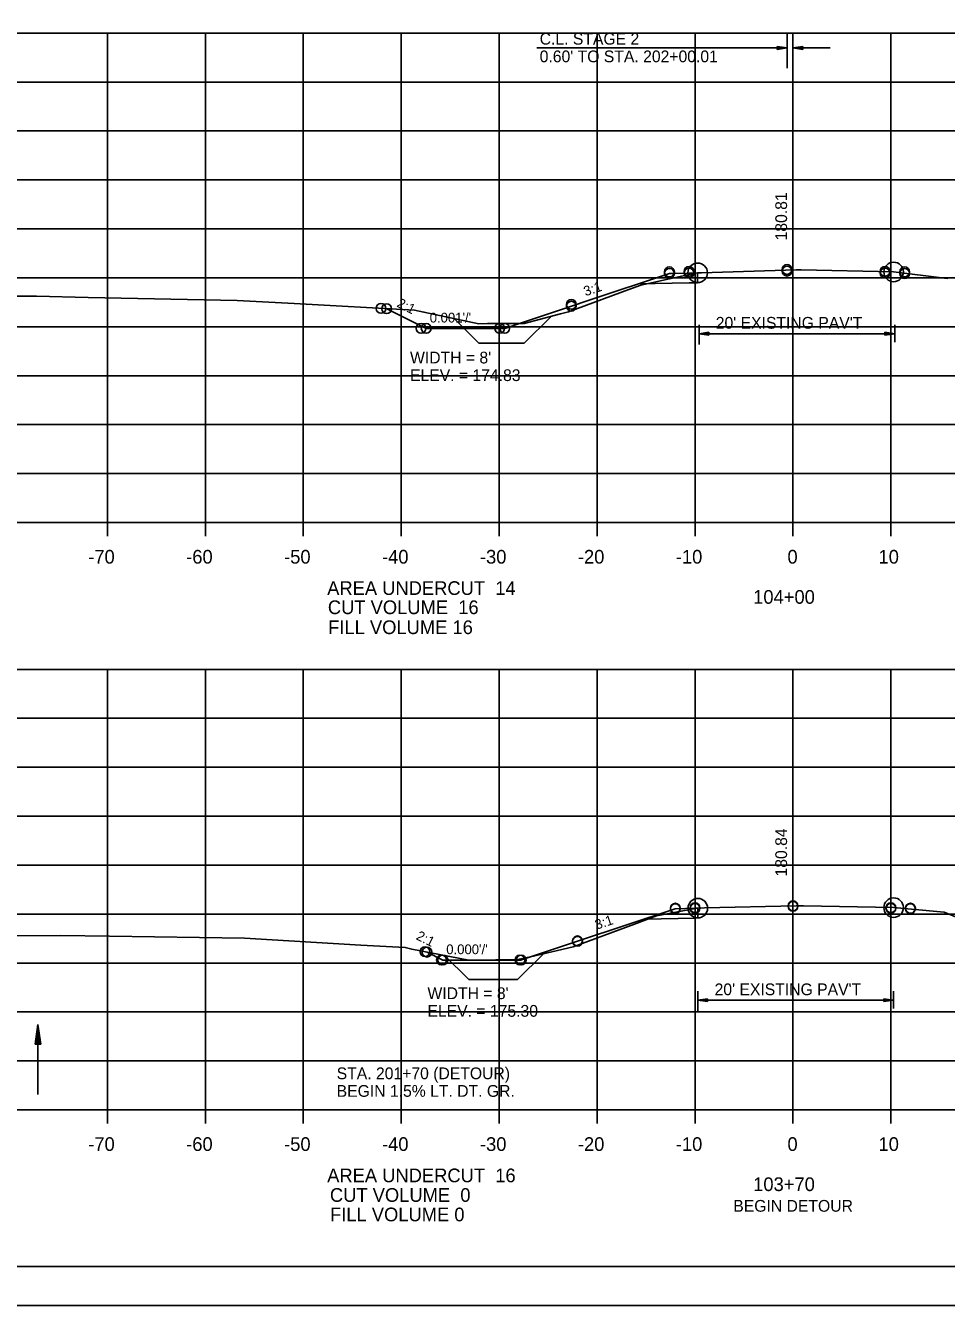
# Model space of a CAD drawing. Extents: x 1372132 to 1372465, y 380083 to 381790.
# Drawn here: x 1372223.7 to 1372317.7, y 380083.5 to 380214.2 of the extents above; entities that cross this region are included whole.
import ezdxf

# ---------------------------------------------------------------- set-up
doc = ezdxf.new("R2010")
doc.units = 0
for name, color, linetype in [('R_Alt Surface', 7, 'Continuous'), ('R_Axis', 7, 'Continuous'), ('R_Axis Annot', 7, 'Continuous'), ('R_Border', 7, 'Continuous'), ('R_Dimension', 7, 'Continuous'), ('R_Draft', 7, 'Continuous'), ('R_Erosion', 7, 'Continuous'), ('R_Exist Surface', 7, 'Continuous'), ('R_Fin Surface', 7, 'Continuous'), ('R_Grid', 7, 'Continuous'), ('R_No Plot', 7, 'Continuous'), ('R_Xsect Elev', 7, 'Continuous'), ('R_Xsect Slope', 7, 'Continuous')]:
    doc.layers.add(name, color=color, linetype=linetype)

msp = doc.modelspace()

# ---------------------------------------------------------------- linework, layer by layer
at = {"layer": 'R_Alt Surface'}
for points in [[(1372292.28, 380187.97), (1372291.4, 380187.95), (1372286.21, 380187.85)], [(1372292.31, 380123.07), (1372292.01, 380123.06), (1372286.82, 380122.96)]]:
    msp.add_lwpolyline(points, dxfattribs=at)
at = {"layer": 'R_Axis'}
for p, q in [((1372162.01, 380163.47), (1372442.01, 380163.47)), ((1372232.01, 380162.07), (1372232.01, 380163.47)), ((1372242.01, 380162.07), (1372242.01, 380163.47)), ((1372252.01, 380162.07), (1372252.01, 380163.47)), ((1372262.01, 380162.07), (1372262.01, 380163.47)), ((1372272.01, 380162.07), (1372272.01, 380163.47)), ((1372282.01, 380162.07), (1372282.01, 380163.47)), ((1372292.01, 380162.07), (1372292.01, 380163.47)), ((1372302.01, 380162.07), (1372302.01, 380163.47)), ((1372312.01, 380162.07), (1372312.01, 380163.47)), ((1372162.01, 380103.47), (1372442.01, 380103.47)), ((1372232.01, 380102.07), (1372232.01, 380103.47)), ((1372242.01, 380102.07), (1372242.01, 380103.47)), ((1372252.01, 380102.07), (1372252.01, 380103.47)), ((1372262.01, 380102.07), (1372262.01, 380103.47)), ((1372272.01, 380102.07), (1372272.01, 380103.47)), ((1372282.01, 380102.07), (1372282.01, 380103.47)), ((1372292.01, 380102.07), (1372292.01, 380103.47)), ((1372302.01, 380102.07), (1372302.01, 380103.47)), ((1372312.01, 380102.07), (1372312.01, 380103.47))]:
    msp.add_line(p, q, dxfattribs=at)
at = {"layer": 'R_Border'}
msp.add_line((1372460.19, 380087.47), (1372144.01, 380087.47), dxfattribs=at)
at = {"layer": 'R_Dimension'}
for p, q in [((1372224.62, 380110.18), (1372224.92, 380112.18)), ((1372224.62, 380110.18), (1372224.92, 380112.18)), ((1372224.67, 380110.18), (1372224.92, 380111.85)), ((1372224.67, 380110.18), (1372224.92, 380111.85)), ((1372224.72, 380110.18), (1372224.92, 380111.51)), ((1372224.72, 380110.18), (1372224.92, 380111.51)), ((1372224.77, 380110.18), (1372224.92, 380111.17)), ((1372224.77, 380110.18), (1372224.92, 380111.17)), ((1372225.22, 380110.18), (1372224.92, 380112.18)), ((1372225.22, 380110.18), (1372224.92, 380112.18)), ((1372225.17, 380110.18), (1372224.92, 380111.85)), ((1372225.17, 380110.18), (1372224.92, 380111.85)), ((1372225.12, 380110.18), (1372224.92, 380111.51)), ((1372225.12, 380110.18), (1372224.92, 380111.51)), ((1372225.07, 380110.18), (1372224.92, 380111.17)), ((1372225.07, 380110.18), (1372224.92, 380111.17)), ((1372224.62, 380110.18), (1372225.22, 380110.18)), ((1372224.62, 380110.18), (1372225.22, 380110.18)), ((1372224.83, 380110.18), (1372224.92, 380110.83)), ((1372224.83, 380110.18), (1372224.92, 380110.83)), ((1372224.88, 380110.18), (1372224.92, 380110.5)), ((1372224.88, 380110.18), (1372224.92, 380110.5)), ((1372225.02, 380110.18), (1372224.92, 380110.83)), ((1372225.02, 380110.18), (1372224.92, 380110.83)), ((1372224.97, 380110.18), (1372224.92, 380110.5)), ((1372224.97, 380110.18), (1372224.92, 380110.5))]:
    msp.add_line(p, q, dxfattribs=at)
at = {"layer": 'R_Draft'}
for p, q in [((1372301.41, 380209.88), (1372301.41, 380213.47)), ((1372302.01, 380213.47), (1372302.01, 380209.88)), ((1372275.87, 380211.96), (1372301.41, 380211.96)), ((1372300.41, 380212.11), (1372301.41, 380211.96)), ((1372300.41, 380212.11), (1372300.41, 380211.81)), ((1372300.41, 380212.11), (1372301.41, 380211.96)), ((1372300.41, 380212.11), (1372300.41, 380211.81)), ((1372300.41, 380212.09), (1372301.25, 380211.96)), ((1372300.41, 380212.09), (1372301.25, 380211.96)), ((1372300.41, 380212.06), (1372301.07, 380211.96)), ((1372300.41, 380212.06), (1372301.07, 380211.96)), ((1372300.41, 380212.04), (1372300.91, 380211.96)), ((1372300.41, 380212.04), (1372300.91, 380211.96)), ((1372300.41, 380212.01), (1372300.74, 380211.96)), ((1372300.41, 380212.01), (1372300.74, 380211.96)), ((1372300.41, 380211.99), (1372300.57, 380211.96)), ((1372300.41, 380211.99), (1372300.57, 380211.96)), ((1372300.41, 380211.81), (1372301.41, 380211.96)), ((1372300.41, 380211.91), (1372300.74, 380211.96)), ((1372300.41, 380211.86), (1372301.07, 380211.96)), ((1372300.41, 380211.84), (1372301.25, 380211.96)), ((1372300.41, 380211.89), (1372300.91, 380211.96)), ((1372300.41, 380211.94), (1372300.57, 380211.96)), ((1372300.41, 380211.81), (1372301.41, 380211.96)), ((1372300.41, 380211.91), (1372300.74, 380211.96)), ((1372300.41, 380211.86), (1372301.07, 380211.96)), ((1372300.41, 380211.84), (1372301.25, 380211.96)), ((1372300.41, 380211.89), (1372300.91, 380211.96)), ((1372300.41, 380211.94), (1372300.57, 380211.96)), ((1372303.01, 380212.11), (1372302.01, 380211.96)), ((1372302.01, 380211.96), (1372305.82, 380211.96)), ((1372303.01, 380211.81), (1372302.01, 380211.96)), ((1372303.01, 380212.09), (1372302.18, 380211.96)), ((1372303.01, 380211.84), (1372302.18, 380211.96)), ((1372303.01, 380212.06), (1372302.35, 380211.96)), ((1372303.01, 380211.86), (1372302.35, 380211.96)), ((1372303.01, 380212.04), (1372302.52, 380211.96)), ((1372303.01, 380211.89), (1372302.52, 380211.96)), ((1372303.01, 380212.01), (1372302.69, 380211.96)), ((1372303.01, 380211.91), (1372302.69, 380211.96)), ((1372303.01, 380211.99), (1372302.86, 380211.96)), ((1372303.01, 380211.94), (1372302.86, 380211.96)), ((1372303.01, 380211.81), (1372303.01, 380212.11)), ((1372292.28, 380188.97), (1372292.28, 380187.97)), ((1372292.43, 380183.67), (1372292.43, 380181.66)), ((1372293.43, 380182.91), (1372292.43, 380182.76)), ((1372293.43, 380182.91), (1372292.43, 380182.76)), ((1372293.43, 380182.88), (1372292.59, 380182.76)), ((1372293.43, 380182.88), (1372292.59, 380182.76)), ((1372293.43, 380182.86), (1372292.77, 380182.76)), ((1372293.43, 380182.86), (1372292.77, 380182.76)), ((1372293.43, 380182.61), (1372293.43, 380182.91)), ((1372293.43, 380182.61), (1372293.43, 380182.91)), ((1372311.41, 380182.91), (1372312.41, 380182.76)), ((1372311.41, 380182.91), (1372311.41, 380182.61)), ((1372311.41, 380182.88), (1372312.24, 380182.76)), ((1372311.41, 380182.86), (1372312.07, 380182.76)), ((1372312.41, 380183.67), (1372312.41, 380181.9)), ((1372312.41, 380182.76), (1372292.43, 380182.76)), ((1372293.43, 380182.61), (1372292.43, 380182.76)), ((1372293.43, 380182.61), (1372292.43, 380182.76)), ((1372292.43, 380181.9), (1372292.43, 380181.9)), ((1372293.43, 380182.63), (1372292.59, 380182.76)), ((1372293.43, 380182.63), (1372292.59, 380182.76)), ((1372293.43, 380182.66), (1372292.77, 380182.76)), ((1372293.43, 380182.66), (1372292.77, 380182.76)), ((1372293.43, 380182.83), (1372292.93, 380182.76)), ((1372293.43, 380182.83), (1372292.93, 380182.76)), ((1372293.43, 380182.68), (1372292.93, 380182.76)), ((1372293.43, 380182.68), (1372292.93, 380182.76)), ((1372293.43, 380182.8), (1372293.1, 380182.76)), ((1372293.43, 380182.8), (1372293.1, 380182.76)), ((1372293.43, 380182.71), (1372293.1, 380182.76)), ((1372293.43, 380182.71), (1372293.1, 380182.76)), ((1372293.43, 380182.78), (1372293.27, 380182.76)), ((1372293.43, 380182.78), (1372293.27, 380182.76)), ((1372293.43, 380182.73), (1372293.27, 380182.76)), ((1372293.43, 380182.73), (1372293.27, 380182.76)), ((1372311.41, 380182.83), (1372311.9, 380182.76)), ((1372311.41, 380182.8), (1372311.73, 380182.76)), ((1372311.41, 380182.78), (1372311.57, 380182.76)), ((1372311.41, 380182.61), (1372312.41, 380182.76)), ((1372311.41, 380182.71), (1372311.73, 380182.76)), ((1372311.41, 380182.66), (1372312.07, 380182.76)), ((1372311.41, 380182.63), (1372312.24, 380182.76)), ((1372311.41, 380182.68), (1372311.9, 380182.76)), ((1372311.41, 380182.73), (1372311.57, 380182.76)), ((1372292.3, 380124.07), (1372292.3, 380123.07)), ((1372292.3, 380115.58), (1372292.3, 380113.57)), ((1372312.29, 380115.58), (1372312.29, 380113.81)), ((1372293.3, 380114.82), (1372292.3, 380114.67)), ((1372293.3, 380114.82), (1372292.3, 380114.67)), ((1372312.29, 380114.67), (1372292.3, 380114.67)), ((1372293.3, 380114.52), (1372292.3, 380114.67)), ((1372293.3, 380114.52), (1372292.3, 380114.67)), ((1372292.3, 380113.81), (1372292.3, 380113.81)), ((1372293.3, 380114.79), (1372292.47, 380114.67)), ((1372293.3, 380114.79), (1372292.47, 380114.67)), ((1372293.3, 380114.54), (1372292.47, 380114.67)), ((1372293.3, 380114.54), (1372292.47, 380114.67)), ((1372293.3, 380114.77), (1372292.64, 380114.67)), ((1372293.3, 380114.77), (1372292.64, 380114.67)), ((1372293.3, 380114.57), (1372292.64, 380114.67)), ((1372293.3, 380114.57), (1372292.64, 380114.67)), ((1372293.3, 380114.74), (1372292.81, 380114.67)), ((1372293.3, 380114.74), (1372292.81, 380114.67)), ((1372293.3, 380114.59), (1372292.81, 380114.67)), ((1372293.3, 380114.59), (1372292.81, 380114.67)), ((1372293.3, 380114.71), (1372292.98, 380114.67)), ((1372293.3, 380114.71), (1372292.98, 380114.67)), ((1372293.3, 380114.62), (1372292.98, 380114.67)), ((1372293.3, 380114.62), (1372292.98, 380114.67)), ((1372293.3, 380114.69), (1372293.15, 380114.67)), ((1372293.3, 380114.69), (1372293.15, 380114.67)), ((1372293.3, 380114.64), (1372293.15, 380114.67)), ((1372293.3, 380114.64), (1372293.15, 380114.67)), ((1372293.3, 380114.52), (1372293.3, 380114.82)), ((1372293.3, 380114.52), (1372293.3, 380114.82)), ((1372311.29, 380114.82), (1372312.29, 380114.67)), ((1372311.29, 380114.82), (1372311.29, 380114.52)), ((1372311.29, 380114.79), (1372312.12, 380114.67)), ((1372311.29, 380114.77), (1372311.95, 380114.67)), ((1372311.29, 380114.74), (1372311.78, 380114.67)), ((1372311.29, 380114.71), (1372311.61, 380114.67)), ((1372311.29, 380114.69), (1372311.44, 380114.67)), ((1372311.29, 380114.52), (1372312.29, 380114.67)), ((1372311.29, 380114.62), (1372311.61, 380114.67)), ((1372311.29, 380114.57), (1372311.95, 380114.67)), ((1372311.29, 380114.54), (1372312.12, 380114.67)), ((1372311.29, 380114.59), (1372311.78, 380114.67)), ((1372311.29, 380114.64), (1372311.44, 380114.67)), ((1372224.92, 380105.04), (1372224.92, 380112.18))]:
    msp.add_line(p, q, dxfattribs=at)
at = {"layer": 'R_Erosion'}
for p, q in [((1372269.94, 380181.78), (1372267.42, 380184.31)), ((1372274.57, 380181.78), (1372277.32, 380184.53)), ((1372269.94, 380181.78), (1372274.57, 380181.78)), ((1372268.9, 380116.78), (1372266.41, 380119.27)), ((1372273.9, 380116.78), (1372276.54, 380119.41)), ((1372268.9, 380116.78), (1372273.9, 380116.78))]:
    msp.add_line(p, q, dxfattribs=at)
at = {"layer": 'R_Exist Surface'}
for points in [[(1372222.51, 380186.6), (1372224.77, 380186.58), (1372230.03, 380186.47), (1372245.27, 380186.15), (1372251.07, 380185.83), (1372263.36, 380185.15), (1372264.32, 380184.96), (1372269.95, 380183.78), (1372270.82, 380183.79), (1372274.57, 380183.79), (1372278.29, 380184.79), (1372279.09, 380184.99), (1372285.25, 380187.28), (1372286.48, 380187.73), (1372292.04, 380188.93), (1372292.28, 380188.98), (1372292.69, 380188.99), (1372302.34, 380189.3), (1372302.84, 380189.29), (1372312.29, 380189.07), (1372317.48, 380188.44), (1372317.82, 380188.4)], [(1372175.77, 380121.19), (1372195.26, 380121.23), (1372227.21, 380121.29), (1372232.22, 380121.2), (1372246.02, 380120.99), (1372257.87, 380120.28), (1372262.42, 380120.07), (1372263.09, 380119.88), (1372268.91, 380118.77), (1372269.44, 380118.77), (1372273.89, 380118.84), (1372275.21, 380119.11), (1372279.58, 380120.12), (1372285.82, 380122.43), (1372288.07, 380123.3), (1372292.02, 380124.03), (1372292.3, 380124.07), (1372292.99, 380124.09), (1372302.34, 380124.32), (1372303.1, 380124.31), (1372312.29, 380124.13), (1372317.08, 380123.7), (1372317.45, 380123.67), (1372325.71, 380120.28)]]:
    msp.add_lwpolyline(points, dxfattribs=at)
at = {"layer": 'R_Fin Surface'}
for points in [[(1372260.53, 380185.31), (1372261.97, 380184.59), (1372264.56, 380183.3), (1372266.93, 380183.3), (1372272.58, 380183.3), (1372274.18, 380183.84), (1372279.39, 380185.57), (1372281.09, 380186.14), (1372289.4, 380188.91), (1372289.6, 380188.91), (1372291.4, 380188.95), (1372292.28, 380188.97)], [(1372264.65, 380119.58), (1372264.65, 380119.58), (1372266.26, 380118.77), (1372266.28, 380118.77), (1372274.26, 380118.77), (1372274.28, 380118.78), (1372280.01, 380120.69), (1372289.99, 380124.01), (1372290.01, 380124.02), (1372292.01, 380124.06), (1372292.01, 380124.06), (1372292.31, 380124.07)]]:
    msp.add_lwpolyline(points, dxfattribs=at)
at = {"layer": 'R_Grid'}
for p, q in [((1372162.01, 380213.47), (1372442.01, 380213.47)), ((1372232.01, 380163.47), (1372232.01, 380213.47)), ((1372242.01, 380163.47), (1372242.01, 380213.47)), ((1372252.01, 380163.47), (1372252.01, 380213.47)), ((1372262.01, 380163.47), (1372262.01, 380213.47)), ((1372272.01, 380163.47), (1372272.01, 380213.47)), ((1372282.01, 380163.47), (1372282.01, 380213.47)), ((1372292.01, 380163.47), (1372292.01, 380213.47)), ((1372302.01, 380163.47), (1372302.01, 380213.47)), ((1372312.01, 380163.47), (1372312.01, 380213.47)), ((1372162.01, 380208.47), (1372442.01, 380208.47)), ((1372162.01, 380203.47), (1372442.01, 380203.47)), ((1372162.01, 380198.47), (1372442.01, 380198.47)), ((1372162.01, 380193.47), (1372442.01, 380193.47)), ((1372162.01, 380188.47), (1372442.01, 380188.47)), ((1372162.01, 380183.47), (1372442.01, 380183.47)), ((1372162.01, 380178.47), (1372442.01, 380178.47)), ((1372162.01, 380173.47), (1372442.01, 380173.47)), ((1372162.01, 380168.47), (1372442.01, 380168.47)), ((1372162.01, 380163.47), (1372442.01, 380163.47)), ((1372162.01, 380148.47), (1372442.01, 380148.47)), ((1372232.01, 380103.47), (1372232.01, 380148.47)), ((1372242.01, 380103.47), (1372242.01, 380148.47)), ((1372252.01, 380103.47), (1372252.01, 380148.47)), ((1372262.01, 380103.47), (1372262.01, 380148.47)), ((1372272.01, 380103.47), (1372272.01, 380148.47)), ((1372282.01, 380103.47), (1372282.01, 380148.47)), ((1372292.01, 380103.47), (1372292.01, 380148.47)), ((1372302.01, 380103.47), (1372302.01, 380148.47)), ((1372312.01, 380103.47), (1372312.01, 380148.47)), ((1372162.01, 380143.47), (1372442.01, 380143.47)), ((1372162.01, 380138.47), (1372442.01, 380138.47)), ((1372162.01, 380133.47), (1372442.01, 380133.47)), ((1372162.01, 380128.47), (1372442.01, 380128.47)), ((1372162.01, 380123.47), (1372442.01, 380123.47)), ((1372162.01, 380118.47), (1372442.01, 380118.47)), ((1372162.01, 380113.47), (1372442.01, 380113.47)), ((1372162.01, 380108.47), (1372442.01, 380108.47)), ((1372162.01, 380103.47), (1372442.01, 380103.47))]:
    msp.add_line(p, q, dxfattribs=at)
at = {"layer": 'R_No Plot'}
msp.add_line((1372131.61, 380083.49), (1372464.95, 380083.49), dxfattribs=at)
for points in [[(1372131.61, 380296.83), (1372464.95, 380296.83), (1372464.95, 380083.49), (1372131.61, 380083.49)], [(1372377.93, 380292.93), (1372377.93, 380283.05), (1372413.67, 380283.05), (1372413.67, 380280.13), (1372436.87, 380280.13), (1372436.87, 380255.8), (1372460.19, 380255.8), (1372460.19, 380087.47), (1372144.01, 380087.47), (1372144.01, 380292.93)]]:
    msp.add_lwpolyline(points, close=True, dxfattribs=at)
for centre, radius in [((1372289.4, 380189.08), 0.5), ((1372289.4, 380188.91), 0.5), ((1372291.4, 380189.12), 0.5), ((1372291.4, 380188.95), 0.5), ((1372292.28, 380188.98), 1), ((1372301.41, 380189.32), 0.5), ((1372301.41, 380189.15), 0.5), ((1372311.42, 380189.12), 0.5), ((1372311.42, 380188.95), 0.5), ((1372312.29, 380189.07), 1), ((1372313.42, 380189.08), 0.5), ((1372313.42, 380188.91), 0.5), ((1372259.94, 380185.34), 0.5), ((1372260.53, 380185.31), 0.5), ((1372279.39, 380185.75), 0.5), ((1372279.39, 380185.57), 0.5), ((1372264.04, 380183.3), 0.5), ((1372264.56, 380183.3), 0.5), ((1372272.06, 380183.3), 0.5), ((1372272.58, 380183.3), 0.5), ((1372290.01, 380124.07), 0.5), ((1372290.01, 380124.02), 0.5), ((1372292.3, 380124.07), 1), ((1372292.01, 380124.11), 0.5), ((1372292.01, 380124.06), 0.5), ((1372302.01, 380124.31), 0.5), ((1372302.01, 380124.26), 0.5), ((1372312.29, 380124.13), 1), ((1372312.01, 380124.11), 0.5), ((1372312.01, 380124.06), 0.5), ((1372314.01, 380124.07), 0.5), ((1372314.01, 380124.02), 0.5), ((1372264.44, 380119.62), 0.5), ((1372280.01, 380120.73), 0.5), ((1372280.01, 380120.69), 0.5), ((1372264.65, 380119.58), 0.5), ((1372266.13, 380118.77), 0.5), ((1372266.26, 380118.77), 0.5), ((1372274.13, 380118.77), 0.5), ((1372274.26, 380118.77), 0.5)]:
    msp.add_circle(centre, radius, dxfattribs=at)
at = {"layer": 'R_Xsect Elev'}
for p, q in [((1372302.01, 380189.29), (1372302.01, 380199.29)), ((1372302.01, 380124.31), (1372302.01, 380134.31))]:
    msp.add_line(p, q, dxfattribs=at)

# ---------------------------------------------------------------- texts
at = {"layer": 'R_Axis Annot'}
for s, p in [('-70', (1372230.05, 380159.27)), ('-60', (1372240.05, 380159.27)), ('-50', (1372250.05, 380159.27)), ('-40', (1372260.05, 380159.27)), ('-30', (1372270.05, 380159.27)), ('-20', (1372280.05, 380159.27)), ('-10', (1372290.05, 380159.27)), ('0', (1372301.45, 380159.27)), ('10', (1372310.75, 380159.27)), ('AREA UNDERCUT  14', (1372254.45, 380156.07)), ('CUT VOLUME  16', (1372254.52, 380154.11)), ('104+00', (1372297.95, 380155.17)), ('FILL VOLUME 16', (1372254.55, 380152.07)), ('-70', (1372230.05, 380099.27)), ('-60', (1372240.05, 380099.27)), ('-50', (1372250.05, 380099.27)), ('-40', (1372260.05, 380099.27)), ('-30', (1372270.05, 380099.27)), ('-20', (1372280.05, 380099.27)), ('-10', (1372290.05, 380099.27)), ('0', (1372301.45, 380099.27)), ('10', (1372310.75, 380099.27)), ('AREA UNDERCUT  16', (1372254.45, 380096.07)), ('103+70', (1372297.95, 380095.17)), ('CUT VOLUME  0', (1372254.73, 380094.07)), ('FILL VOLUME 0', (1372254.74, 380092.08))]:
    msp.add_text(s, height=1.4, dxfattribs=at).set_placement(p)
at = {"layer": 'R_Dimension'}
for s, p in [("WIDTH = 8'", (1372262.91, 380179.72)), ('ELEV. = 174.83', (1372262.91, 380177.92)), ("WIDTH = 8'", (1372264.69, 380114.78)), ('ELEV. = 175.30', (1372264.69, 380112.98))]:
    msp.add_text(s, height=1.2, dxfattribs=at).set_placement(p)
at = {"layer": 'R_Draft'}
for s, p in [('C.L. STAGE 2', (1372276.15, 380212.29)), ("0.60' TO STA. 202+00.01", (1372276.15, 380210.49)), ("20' EXISTING PAV'T", (1372294.13, 380183.27)), ("20' EXISTING PAV'T", (1372294.01, 380115.18)), ('STA. 201+70 (DETOUR)', (1372255.42, 380106.6)), ('BEGIN 1.5% LT. DT. GR.', (1372255.42, 380104.8)), ('BEGIN DETOUR', (1372295.92, 380093.06))]:
    msp.add_text(s, height=1.2, rotation=360, dxfattribs=at).set_placement(p)
at = {"layer": 'R_Xsect Elev'}
for s, p in [('180.81', (1372301.41, 380192.29)), ('180.84', (1372301.41, 380127.31))]:
    msp.add_text(s, height=1.2, rotation=90, dxfattribs=at).set_placement(p)
at = {"layer": 'R_Xsect Slope'}
for s, rotation, p in [('3:1', 18.4293, (1372280.83, 380186.58)), ('2:1', 333.5195, (1372261.48, 380185.55)), ("0.001'/'", 0.0387, (1372264.92, 380183.9)), ('3:1', 18.4343, (1372281.98, 380121.87)), ('2:1', 333.4349, (1372263.45, 380120.92)), ("0.000'/'", 360, (1372266.61, 380119.37))]:
    msp.add_text(s, height=1, rotation=rotation, dxfattribs=at).set_placement(p)

doc.saveas('drawing.dxf')
